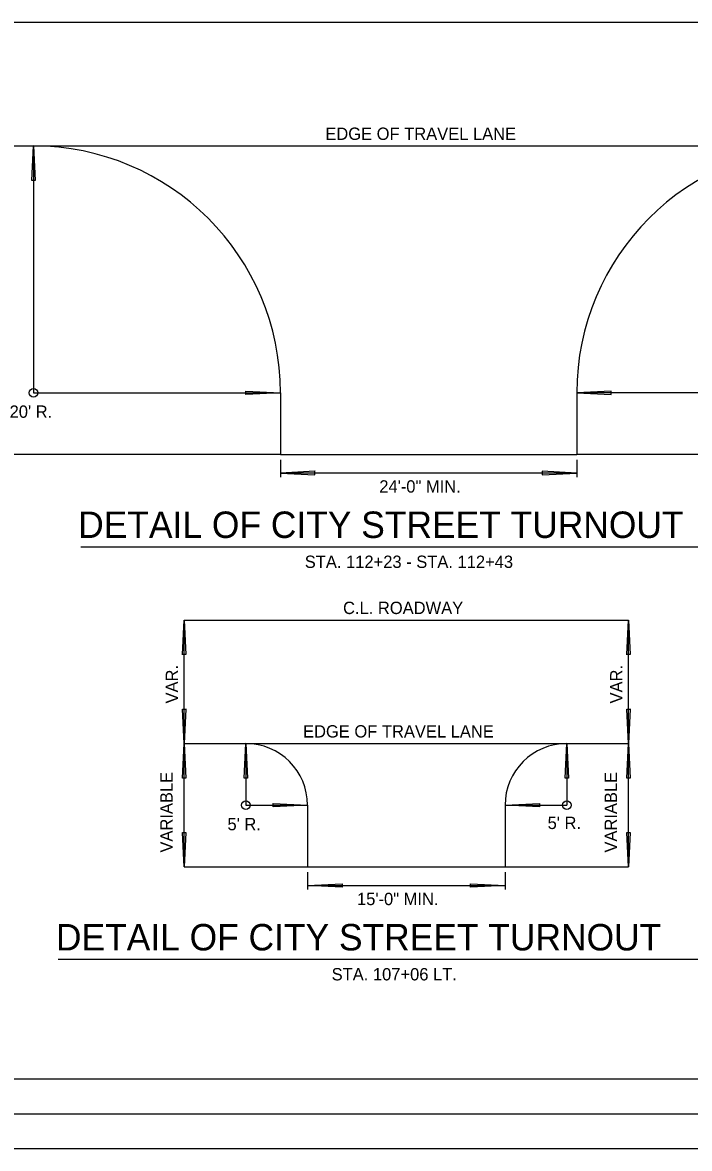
# Model space of a CAD drawing. Extents: x 1944905 to 1956777, y 763871 to 764977.
# Drawn here: x 1947573 to 1947951, y 763871 to 764509 of the extents above; entities that cross this region are included whole.
import ezdxf

# ---------------------------------------------------------------- set-up
doc = ezdxf.new("R2010")
doc.units = 0
doc.layers.add('Default', color=7, linetype='Continuous')
doc.layers.add('E_Existing ROW', color=7, linetype='Continuous')

msp = doc.modelspace()

# ---------------------------------------------------------------- linework, layer by layer
at = {"layer": 'Default'}
for p, q in [((1948061.85, 764509.29), (1947543.85, 764509.29)), ((1947577.88, 764419.74), (1947578.85, 764439.29)), ((1947578.85, 764439.29), (1948026.85, 764439.29)), ((1947578.85, 764439.29), (1947579.83, 764419.74)), ((1947578.85, 764439.29), (1947578.85, 764299.29)), ((1947579.83, 764419.74), (1947577.88, 764419.74)), ((1947577.88, 764419.68), (1947577.88, 764419.74)), ((1947578.85, 764299.29), (1947718.85, 764299.29)), ((1947699.24, 764300.27), (1947699.31, 764300.27)), ((1947699.31, 764300.27), (1947718.85, 764299.29)), ((1947699.31, 764298.31), (1947699.31, 764300.27)), ((1947718.85, 764299.29), (1947699.31, 764298.31)), ((1947906.4, 764300.27), (1947886.85, 764299.29)), ((1948026.85, 764299.29), (1947886.85, 764299.29)), ((1947886.85, 764299.29), (1947906.4, 764298.31)), ((1947906.4, 764298.31), (1947906.4, 764300.27)), ((1947906.47, 764300.27), (1947906.4, 764300.27)), ((1947718.85, 764264.29), (1947543.85, 764264.29)), ((1947718.85, 764264.29), (1947886.85, 764264.29)), ((1948061.85, 764264.29), (1947886.85, 764264.29)), ((1947718.85, 764261.29), (1947718.85, 764251.51)), ((1947886.85, 764261.29), (1947886.85, 764251.51)), ((1947738.4, 764254.74), (1947718.85, 764253.76)), ((1947718.85, 764253.76), (1947738.4, 764252.78)), ((1947886.85, 764253.76), (1947718.85, 764253.76)), ((1947738.4, 764252.78), (1947738.4, 764254.74)), ((1947738.47, 764254.74), (1947738.4, 764254.74)), ((1947867.24, 764252.78), (1947867.31, 764252.78)), ((1947886.85, 764253.76), (1947867.31, 764254.74)), ((1947867.31, 764254.74), (1947867.31, 764252.78)), ((1947867.31, 764252.78), (1947886.85, 764253.76)), ((1947605.64, 764211.94), (1948001.01, 764211.94)), ((1947663.24, 764150.79), (1947664.22, 764170.34)), ((1947664.22, 764170.34), (1947916.22, 764170.34)), ((1947664.22, 764100.34), (1947664.22, 764170.34)), ((1947664.22, 764170.34), (1947665.2, 764150.79)), ((1947915.24, 764150.79), (1947916.22, 764170.34)), ((1947916.22, 764100.34), (1947916.22, 764170.34)), ((1947916.22, 764170.34), (1947917.2, 764150.79)), ((1947665.2, 764150.79), (1947663.24, 764150.79)), ((1947663.24, 764150.73), (1947663.24, 764150.79)), ((1947917.2, 764150.79), (1947915.24, 764150.79)), ((1947915.24, 764150.73), (1947915.24, 764150.79)), ((1947664.22, 764100.34), (1947663.24, 764119.89)), ((1947663.24, 764119.89), (1947665.2, 764119.89)), ((1947665.2, 764119.89), (1947664.22, 764100.34)), ((1947665.2, 764119.95), (1947665.2, 764119.89)), ((1947916.22, 764100.34), (1947915.24, 764119.89)), ((1947915.24, 764119.89), (1947917.2, 764119.89)), ((1947917.2, 764119.89), (1947916.22, 764100.34)), ((1947917.2, 764119.95), (1947917.2, 764119.89)), ((1947663.24, 764080.79), (1947664.22, 764100.34)), ((1947664.22, 764100.34), (1947665.2, 764080.79)), ((1947664.22, 764030.34), (1947664.22, 764099.75)), ((1947698.24, 764080.79), (1947699.22, 764100.34)), ((1947699.22, 764100.34), (1947881.22, 764100.34)), ((1947699.22, 764100.34), (1947700.2, 764080.79)), ((1947699.22, 764100.34), (1947699.22, 764065.34)), ((1947880.24, 764080.79), (1947881.22, 764100.34)), ((1947881.22, 764100.34), (1947881.22, 764065.34)), ((1947881.22, 764100.34), (1947882.2, 764080.79)), ((1947915.24, 764080.79), (1947916.22, 764100.34)), ((1947916.22, 764100.34), (1947917.2, 764080.79)), ((1947916.22, 764030.34), (1947916.22, 764099.75)), ((1947665.2, 764080.79), (1947663.24, 764080.79)), ((1947663.24, 764080.73), (1947663.24, 764080.79)), ((1947700.2, 764080.79), (1947698.24, 764080.79)), ((1947698.24, 764080.73), (1947698.24, 764080.79)), ((1947882.2, 764080.79), (1947880.24, 764080.79)), ((1947880.24, 764080.73), (1947880.24, 764080.79)), ((1947917.2, 764080.79), (1947915.24, 764080.79)), ((1947915.24, 764080.73), (1947915.24, 764080.79)), ((1947699.22, 764065.34), (1947734.22, 764065.34)), ((1947714.61, 764066.32), (1947714.67, 764066.32)), ((1947714.67, 764066.32), (1947734.22, 764065.34)), ((1947714.67, 764064.36), (1947714.67, 764066.32)), ((1947734.22, 764065.34), (1947714.67, 764064.36)), ((1947846.22, 764065.34), (1947865.77, 764066.32)), ((1947846.22, 764065.34), (1947881.22, 764065.34)), ((1947865.77, 764064.36), (1947846.22, 764065.34)), ((1947865.77, 764066.32), (1947865.77, 764064.36)), ((1947865.83, 764064.36), (1947865.77, 764064.36)), ((1947664.22, 764030.34), (1947663.24, 764049.89)), ((1947663.24, 764049.89), (1947665.2, 764049.89)), ((1947665.2, 764049.89), (1947664.22, 764030.34)), ((1947665.2, 764049.95), (1947665.2, 764049.89)), ((1947916.22, 764030.34), (1947915.24, 764049.89)), ((1947915.24, 764049.89), (1947917.2, 764049.89)), ((1947917.2, 764049.89), (1947916.22, 764030.34)), ((1947917.2, 764049.95), (1947917.2, 764049.89)), ((1947664.22, 764030.34), (1947734.22, 764030.34)), ((1947734.22, 764030.34), (1947846.22, 764030.34)), ((1947734.22, 764027.35), (1947734.22, 764017.56)), ((1947846.22, 764030.34), (1947916.22, 764030.34)), ((1947846.22, 764027.35), (1947846.22, 764017.56)), ((1947734.22, 764019.81), (1947753.77, 764020.79)), ((1947753.77, 764018.83), (1947734.22, 764019.81)), ((1947734.22, 764019.81), (1947846.22, 764019.81)), ((1947753.77, 764020.79), (1947753.77, 764018.83)), ((1947826.61, 764020.79), (1947826.67, 764020.79)), ((1947826.67, 764020.79), (1947846.22, 764019.81)), ((1947826.67, 764018.83), (1947826.67, 764020.79)), ((1947846.22, 764019.81), (1947826.67, 764018.83)), ((1947753.83, 764018.83), (1947753.77, 764018.83)), ((1947592.86, 763978), (1947988.57, 763978)), ((1948232.12, 763910.07), (1946651.22, 763910.07)), ((1946618.38, 763890.36), (1948232.12, 763890.36)), ((1946618.38, 763870.67), (1948232.12, 763870.67))]:
    msp.add_line(p, q, dxfattribs=at)
for centre in [(1947578.85, 764299.29), (1947699.22, 764065.34), (1947881.22, 764065.34)]:
    msp.add_circle(centre, 2.44, dxfattribs=at)
at = {"layer": 'E_Existing ROW'}
for p, q in [((1947543.85, 764439.29), (1947578.85, 764439.29)), ((1947718.85, 764299.29), (1947718.85, 764264.29)), ((1947886.85, 764299.29), (1947886.85, 764264.29)), ((1947664.22, 764100.34), (1947699.22, 764100.34)), ((1947881.22, 764100.34), (1947916.22, 764100.34)), ((1947734.22, 764065.34), (1947734.22, 764030.34)), ((1947846.22, 764065.34), (1947846.22, 764030.34))]:
    msp.add_line(p, q, dxfattribs=at)
for centre, radius, start, end in [((1947578.85, 764299.29), 140, 0, 90), ((1948026.85, 764299.29), 140, 90, 180), ((1947699.22, 764065.34), 35, 0, 90), ((1947881.22, 764065.34), 35, 90, 180)]:
    msp.add_arc(centre, radius, start, end, dxfattribs=at)

# ---------------------------------------------------------------- texts
at = {"layer": 'Default'}
for s, height, p in [('EDGE OF TRAVEL LANE', 7, (1947744.28, 764442.71)), ("20' R.", 7, (1947565.27, 764285.09)), ('24\'-0" MIN.', 7, (1947774.89, 764242.66)), ('DETAIL OF CITY STREET TURNOUT', 15, (1947604.17, 764216.94)), ('STA. 112+23 - STA. 112+43', 7, (1947732.64, 764199.94)), ('C.L. ROADWAY', 7, (1947754.34, 764173.79)), ('EDGE OF TRAVEL LANE', 7, (1947731.65, 764103.76)), ("5' R.", 7, (1947688.81, 764051.14)), ("5' R.", 7, (1947870.34, 764051.85)), ('15\'-0" MIN.', 7, (1947762.26, 764008.71)), ('DETAIL OF CITY STREET TURNOUT', 15, (1947591.54, 763983)), ('STA. 107+06 LT.', 7, (1947747.87, 763966))]:
    msp.add_text(s, height=height, dxfattribs=at).set_placement(p)
for s, p in [('VAR.', (1947660.8, 764123.06)), ('VAR.', (1947912.8, 764123.06)), ('VARIABLE', (1947657.68, 764038.5)), ('VARIABLE', (1947909.68, 764038.5))]:
    msp.add_text(s, height=7, rotation=90, dxfattribs=at).set_placement(p)

doc.saveas('drawing.dxf')
